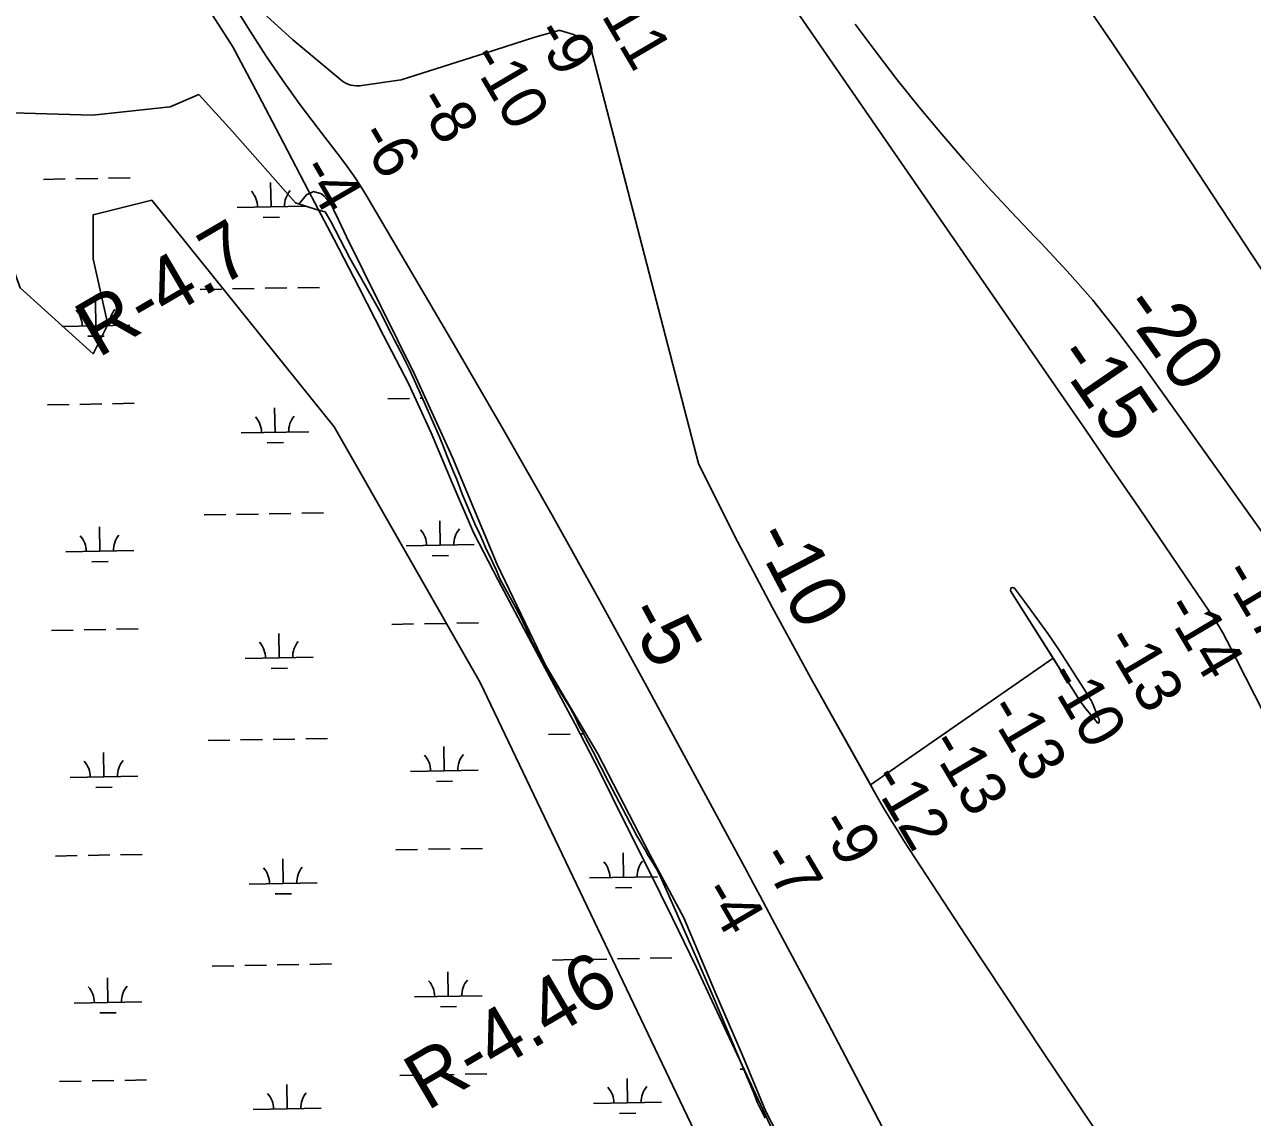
# Model space of a CAD drawing. Extents: x 3914892 to 3953151, y 242587 to 268572.
# Drawn here: x 3932283 to 3934093, y 262785 to 264396 of the extents above; entities that cross this region are included whole.
import ezdxf

# ---------------------------------------------------------------- set-up
doc = ezdxf.new("R2010")
doc.units = 0
for name, color, linetype in [('V-RIVR-EDGE', 7, 'Continuous'), ('V-RIVR-RANG', 7, 'Continuous'), ('V-RIVR-RANG-IDEN', 7, 'Continuous'), ('V-RRAP-FSHR', 7, 'Continuous'), ('V-SITE-VEGE', 7, 'Continuous'), ('V-TOPO-DPTH', 7, 'Continuous'), ('V-TOPO-MINR', 7, 'Continuous'), ('V-TOPO-MINR-IDEN', 7, 'Continuous'), ('V-WETL-SWMP', 7, 'Continuous')]:
    doc.layers.add(name, color=color, linetype=linetype)

msp = doc.modelspace()

# ---------------------------------------------------------------- linework, layer by layer
at = {"layer": 'V-RIVR-EDGE'}
for points in [[(3932741.6, 264116.7), (3932738.6, 264122.1), (3932736.6, 264127.8), (3932731.1, 264135.2), (3932728.1, 264139.1), (3932724.4, 264143.6), (3932720.6, 264146.6), (3932708.8, 264150.3), (3932698.2, 264145.2), (3932693.8, 264139.8), (3932689.3, 264134.6), (3932687.2, 264131.7)], [(3932741.7, 264116.7), (3932757, 264083.5), (3932857.4, 263880.8), (3932913.7, 263757.9), (3932979.2, 263600.3), (3933050.8, 263451.9), (3933127.6, 263320.8), (3933204.4, 263172.4), (3933254.6, 263079.2), (3933300.6, 262969.7), (3933340.6, 262877.6), (3933375.4, 262793.6), (3933432.7, 262683)]]:
    msp.add_lwpolyline(points, dxfattribs=at)
at = {"layer": 'V-RRAP-FSHR'}
msp.add_lwpolyline([(3932546.2, 264430.8), (3932589.8, 264363.8), (3932627.1, 264293.4), (3932664.2, 264222.2), (3932701.3, 264151.3), (3932738.4, 264080.4), (3932775.4, 264009.3), (3932811.6, 263938.1), (3932848.9, 263866.9), (3932882.1, 263794.5), (3932913.1, 263720.8), (3932944.3, 263647.2), (3932980.9, 263576.9), (3933018.8, 263505.6), (3933056.7, 263435.2), (3933094.6, 263364.7), (3933131.2, 263293.6), (3933166.7, 263221.9), (3933202.3, 263150.3), (3933237.9, 263078.6), (3933272.9, 263006.7), (3933306.8, 262934.3), (3933340.8, 262861.8), (3933374.7, 262789.3), (3933408.6, 262716.9)], dxfattribs=at)
at = {"layer": 'V-SITE-VEGE'}
msp.add_lwpolyline([(3934289.5, 260701.2), (3933891.1, 261325.9), (3933417.4, 262456.9), (3932954.5, 263426.4), (3932739.2, 263803.4), (3932470, 264137.3), (3932383.9, 264115.7), (3932383.9, 264051.1), (3932405.4, 263954.2), (3932383.9, 263911.1), (3932276.2, 264008), (3932190.1, 264245), (3932141.4, 264285.3)], dxfattribs=at)
at = {"layer": 'V-TOPO-DPTH'}
for points in [[(3933842.2, 264433.8), (3933887, 264368), (3933931.2, 264301.7), (3934301, 263739.5)], [(3933842.2, 264433.8), (3933887, 264368), (3933931.2, 264301.7), (3934301, 263739.5)], [(3933527.9, 263279.1), (3933442, 263432.6), (3933384.9, 263537.1), (3933329.4, 263642.5), (3933276.3, 263749), (3933117.1, 264363.8), (3933110.2, 264371.5), (3933101.6, 264377.2), (3933091.8, 264381.6), (3933072.3, 264387.5), (3933071.3, 264387.7), (3933070.3, 264387.8), (3933035.1, 264377.8), (3932961.5, 264354.3), (3932838, 264315.2), (3932776.6, 264306.2), (3932772.1, 264306.3), (3932767.7, 264306.5), (3932763.4, 264307.2), (3932759.3, 264308.4), (3932755.5, 264310.3), (3932751.9, 264312.7), (3932678.2, 264373.8), (3932639.8, 264408.9)], [(3933507.4, 264397.1), (3933538.1, 264355.8), (3933569.3, 264315), (3933601.5, 264274.9), (3933634.3, 264235.3), (3933668, 264196.4), (3933702.1, 264157.9), (3933737.1, 264120.3), (3933772.7, 264083.1), (3933780.8, 264074.7), (3933819.8, 264032.8), (3933857.5, 263989.8), (3933893.2, 263945.2), (3933927.5, 263899.4), (3934124, 263624.5)], [(3934124, 263624.5), (3933927.5, 263899.4), (3933893.2, 263945.2), (3933857.5, 263989.8), (3933819.8, 264032.8), (3933780.8, 264074.7), (3933772.7, 264083.1), (3933737.1, 264120.3), (3933702.1, 264157.9), (3933668, 264196.4), (3933634.3, 264235.3), (3933601.5, 264274.9), (3933569.3, 264315), (3933538.1, 264355.8), (3933507.4, 264397.1)], [(3933855.1, 263399.6), (3933853.4, 263402.5), (3933851.7, 263405.5), (3933823.8, 263449.3), (3933807.8, 263473.9), (3933791.3, 263498.2), (3933774.3, 263522.1), (3933756.9, 263545.8), (3933742.2, 263565.2), (3933739.4, 263566.1), (3933737.4, 263565.9), (3933736.5, 263564.1), (3933736.4, 263561.2), (3933795, 263468.3), (3933799, 263462.1), (3933529.9, 263275.5), (3933527.9, 263279.1)], [(3933529.9, 263275.5), (3933799, 263462.1), (3933839, 263398.8), (3933841.1, 263395.6), (3933843.2, 263392.6), (3933845.5, 263389.6), (3933847.8, 263386.7), (3933864.5, 263366.8), (3933865.2, 263366.4), (3933865.7, 263366.3), (3933866.3, 263366.6), (3933866.8, 263367.1), (3933867.2, 263369.1), (3933866.8, 263371), (3933857.9, 263393.4), (3933856.5, 263396.5), (3933855.1, 263399.6)], [(3934096.4, 262422), (3934086.3, 262436.7), (3933900.3, 262709.1), (3933842.4, 262794.4), (3933784.8, 262880), (3933727.8, 262965.9), (3933671.1, 263052), (3933579.1, 263192.9), (3933568.9, 263208.9), (3933558.9, 263225), (3933549.2, 263241.3), (3933539.8, 263257.8), (3933529.9, 263275.5)]]:
    msp.add_lwpolyline(points, dxfattribs=at)
at = {"layer": 'V-TOPO-MINR'}
for points in [[(3932375.9, 264768.2), (3932615.1, 264386.9), (3932638.9, 264350.1), (3932663.5, 264313.8), (3932689, 264278.3), (3932715.3, 264243.2), (3932748.3, 264200.5), (3932758.4, 264187), (3932768.1, 264173.3), (3932777.2, 264159.1), (3932786, 264144.8), (3932915.9, 263924.1), (3932988.6, 263798.8), (3933060.5, 263673), (3933131, 263546.4), (3933200.5, 263419.4), (3933347.8, 263146.8), (3933357.2, 263129.3), (3933366.6, 263111.9), (3933376, 263094.4), (3933385.4, 263076.9), (3933461.8, 262933.8), (3933508.8, 262844.5), (3933555.2, 262754.8)], [(3933359, 264506.7), (3933806.5, 263857.3), (3933846.1, 263799.6), (3933885.7, 263741.9), (3933925.3, 263684.1), (3933964.7, 263626.3), (3934029.3, 263531.5), (3934036.2, 263521), (3934042.8, 263510.2), (3934049.1, 263499.3), (3934055, 263488.2), (3934123.6, 263354)], [(3933842.2, 264433.8), (3933887, 264368), (3933931.2, 264301.7), (3934301, 263739.5)], [(3932639.8, 264408.9), (3932678.2, 264373.8), (3932751.9, 264312.7), (3932755.5, 264310.3), (3932759.3, 264308.4), (3932763.4, 264307.2), (3932767.7, 264306.5), (3932772.1, 264306.3), (3932776.6, 264306.2), (3932838, 264315.2), (3932961.5, 264354.3), (3933035.1, 264377.8), (3933070.3, 264387.8), (3933071.3, 264387.7), (3933072.3, 264387.5), (3933091.8, 264381.6), (3933101.6, 264377.2), (3933110.2, 264371.5), (3933117.1, 264363.8), (3933276.3, 263749), (3933329.4, 263642.5), (3933384.9, 263537.1), (3933442, 263432.6), (3933539.8, 263257.8), (3933549.2, 263241.3), (3933558.9, 263225), (3933568.9, 263208.9), (3933579.1, 263192.9), (3933671.1, 263052), (3933727.8, 262965.9), (3933784.8, 262880), (3933842.4, 262794.4), (3933900.3, 262709.1)], [(3933507.4, 264397.1), (3933538.1, 264355.8), (3933569.3, 264315), (3933601.5, 264274.9), (3933634.3, 264235.3), (3933668, 264196.4), (3933702.1, 264157.9), (3933737.1, 264120.3), (3933772.7, 264083.1), (3933780.8, 264074.7), (3933819.8, 264032.8), (3933857.5, 263989.8), (3933893.2, 263945.2), (3933927.5, 263899.4), (3934124, 263624.5)], [(3933855.1, 263399.6), (3933856.5, 263396.5), (3933857.9, 263393.4), (3933866.8, 263371), (3933867.2, 263369.1), (3933866.8, 263367.1), (3933866.3, 263366.6), (3933865.7, 263366.3), (3933865.2, 263366.4), (3933864.5, 263366.8), (3933847.8, 263386.7), (3933845.5, 263389.6), (3933843.2, 263392.6), (3933841.1, 263395.6), (3933839, 263398.8), (3933736.4, 263561.2), (3933736.5, 263564.1), (3933737.4, 263565.9), (3933739.4, 263566.1), (3933742.2, 263565.2), (3933756.9, 263545.8), (3933774.3, 263522.1), (3933791.3, 263498.2), (3933807.8, 263473.9), (3933823.8, 263449.3), (3933851.7, 263405.5), (3933853.4, 263402.5), (3933855.1, 263399.6)]]:
    msp.add_lwpolyline(points, dxfattribs=at)
at = {"layer": 'V-WETL-SWMP'}
for p, q in [((3932310.4, 264168.2), (3932342.4, 264168.8)), ((3932358.4, 264169.1), (3932390.4, 264169.6)), ((3932406.4, 264169.9), (3932438.4, 264170.5)), ((3932646, 264127.8), (3932645.4, 264163.8)), ((3932596, 264126.9), (3932696, 264128.7)), ((3932634.3, 264112.1), (3932658.3, 264112.5)), ((3932541.3, 264005.8), (3932573.3, 264006.4)), ((3932589.3, 264006.7), (3932621.3, 264007.2)), ((3932637.3, 264007.5), (3932669.3, 264008.1)), ((3932685.3, 264008.4), (3932717.3, 264008.9)), ((3932387.7, 263952.3), (3932387, 263988.3)), ((3932337.7, 263951.4), (3932437.6, 263953.2)), ((3932375.9, 263936.7), (3932399.9, 263937.1)), ((3932316.3, 263835.6), (3932348.3, 263836.1)), ((3932364.3, 263836.4), (3932396.3, 263837)), ((3932412.3, 263837.3), (3932444.3, 263837.9)), ((3932651.9, 263795.1), (3932651.3, 263831.1)), ((3932818.2, 263844.5), (3932850.1, 263845.1)), ((3932866.1, 263845.4), (3932869.3, 263845.5)), ((3932602, 263794.2), (3932701.9, 263796)), ((3932640.2, 263779.5), (3932664.2, 263779.9)), ((3932547.3, 263673.2), (3932579.3, 263673.7)), ((3932595.3, 263674), (3932627.3, 263674.6)), ((3932643.3, 263674.9), (3932675.2, 263675.5)), ((3932691.2, 263675.8), (3932723.2, 263676.3)), ((3932393.6, 263619.7), (3932393, 263655.7)), ((3932895.4, 263628.7), (3932894.8, 263664.6)), ((3932343.6, 263618.8), (3932443.6, 263620.6)), ((3932845.4, 263627.8), (3932945.4, 263629.5)), ((3932883.7, 263613), (3932907.7, 263613.4)), ((3932381.9, 263604), (3932405.9, 263604.5)), ((3932322.3, 263502.9), (3932354.3, 263503.5)), ((3932370.3, 263503.8), (3932402.3, 263504.4)), ((3932418.3, 263504.7), (3932450.3, 263505.2)), ((3932824.1, 263511.9), (3932856.1, 263512.5)), ((3932872.1, 263512.8), (3932904.1, 263513.4)), ((3932920.1, 263513.6), (3932952.1, 263514.2)), ((3932657.9, 263462.5), (3932657.3, 263498.5)), ((3932607.9, 263461.6), (3932707.9, 263463.4)), ((3932646.2, 263446.9), (3932670.2, 263447.3)), ((3932553.2, 263340.6), (3932585.2, 263341.1)), ((3932601.2, 263341.4), (3932633.2, 263342)), ((3932649.2, 263342.3), (3932681.2, 263342.8)), ((3932697.2, 263343.1), (3932729.2, 263343.7)), ((3933055, 263349.5), (3933087, 263350.1)), ((3933103, 263350.4), (3933106.7, 263350.5)), ((3932399.6, 263287.1), (3932398.9, 263323)), ((3932901.4, 263296), (3932900.7, 263332)), ((3932349.6, 263286.2), (3932449.5, 263287.9)), ((3932851.4, 263295.1), (3932951.4, 263296.9)), ((3932387.8, 263271.4), (3932411.8, 263271.8)), ((3932889.7, 263280.4), (3932913.7, 263280.8)), ((3932830.1, 263179.3), (3932862, 263179.9)), ((3932878, 263180.2), (3932910, 263180.7)), ((3932926, 263181), (3932958, 263181.6)), ((3932328.2, 263170.3), (3932360.2, 263170.9)), ((3932376.2, 263171.2), (3932408.2, 263171.8)), ((3932424.2, 263172), (3932456.2, 263172.6)), ((3932663.8, 263129.9), (3932663.2, 263165.9)), ((3933165.7, 263138.9), (3933165, 263174.9)), ((3932613.9, 263129), (3932713.8, 263130.8)), ((3933115.7, 263138), (3933215.7, 263139.8)), ((3933154, 263123.2), (3933177.9, 263123.7)), ((3932652.1, 263114.3), (3932676.1, 263114.7)), ((3933061, 263016.9), (3933093, 263017.5)), ((3933109, 263017.8), (3933141, 263018.3)), ((3933157, 263018.6), (3933189, 263019.2)), ((3933205, 263019.5), (3933237, 263020.1)), ((3932559.2, 263007.9), (3932591.2, 263008.5)), ((3932607.2, 263008.8), (3932639.2, 263009.4)), ((3932655.2, 263009.6), (3932687.1, 263010.2)), ((3932703.1, 263010.5), (3932735.1, 263011.1)), ((3932907.3, 262963.4), (3932906.7, 262999.4)), ((3932405.5, 262954.4), (3932404.9, 262990.4)), ((3932857.3, 262962.5), (3932957.3, 262964.3)), ((3932355.5, 262953.5), (3932455.5, 262955.3)), ((3932895.6, 262947.8), (3932919.6, 262948.2)), ((3932393.8, 262938.8), (3932417.8, 262939.2)), ((3933337.8, 262855.7), (3933343.1, 262855.8)), ((3932334.2, 262837.7), (3932366.2, 262838.3)), ((3932382.2, 262838.6), (3932414.2, 262839.1)), ((3932430.2, 262839.4), (3932462.2, 262840)), ((3932669.8, 262797.3), (3932669.2, 262833.3)), ((3932836, 262846.7), (3932868, 262847.3)), ((3932884, 262847.5), (3932916, 262848.1)), ((3932932, 262848.4), (3932964, 262849)), ((3933171.6, 262806.3), (3933171, 262842.2)), ((3932619.8, 262796.4), (3932719.8, 262798.2)), ((3933121.6, 262805.4), (3933221.6, 262807.1)), ((3933159.9, 262790.6), (3933183.9, 262791))]:
    msp.add_line(p, q, dxfattribs=at)
for points in [[(3932725.9, 264120.3), (3932712.5, 264123.5), (3932682, 264133.4), (3932589.1, 264238.9), (3932539.6, 264293.3), (3932497.5, 264275.3), (3932382.5, 264262.8), (3932230.7, 264267.1)], [(3933374.7, 262783.5), (3933363.2, 262806.4), (3933356.7, 262822.8), (3933343.3, 262855.2), (3933299.4, 262959.7), (3933273.8, 263018.8), (3933240.3, 263094.5), (3933222.7, 263134), (3933218.3, 263144), (3933214.4, 263151.4), (3933210.6, 263157.6), (3933205.5, 263165.6), (3933202.2, 263171.2), (3933197.5, 263179.3), (3933193.1, 263186.6), (3933188.1, 263194.9), (3933185.3, 263199.8), (3933143.5, 263279.6), (3933120.3, 263325), (3933110, 263344.2), (3933105, 263353.7), (3933101.5, 263359.8), (3933097.8, 263367.2), (3933094.8, 263374.1), (3933090.9, 263381.6), (3933087, 263388.8), (3933082.8, 263395.5), (3933078.6, 263402), (3933074.6, 263408.4), (3933066.2, 263422.2), (3933056.7, 263440.2), (3933050.5, 263450.9), (3933043.4, 263463.1), (3933038.6, 263471.7), (3933032, 263483.8), (3933029.4, 263488.8), (3933026, 263496.4), (3933022, 263505.9), (3933017.8, 263515), (3933012.3, 263525.9), (3933006.3, 263537.1), (3932983.5, 263579), (3932978.5, 263591.2), (3932974.1, 263600.9), (3932968.9, 263611.3), (3932963.7, 263622), (3932958.6, 263633.6), (3932953.2, 263645.7), (3932946.7, 263660), (3932928.5, 263702.7), (3932920.1, 263725.6), (3932915.1, 263736.7), (3932910.1, 263748.5), (3932905.4, 263760.9), (3932900.5, 263773.5), (3932894.6, 263788.4), (3932868.5, 263847.3), (3932849.9, 263887.7), (3932845.4, 263897.5), (3932840.6, 263907.1), (3932836.3, 263915.3), (3932831.9, 263923.7), (3932828.1, 263931.2), (3932823.1, 263940.7), (3932806.2, 263973.6), (3932762.2, 264051.9), (3932733.9, 264105.8), (3932725.9, 264120.3)]]:
    msp.add_lwpolyline(points, dxfattribs=at)
for centre, start, end in [((3932590.8, 264127.2), 0.2532, 41.7968), ((3932701.2, 264129.2), 140.2532, 181.7968), ((3932332.4, 263951.8), 0.2532, 41.7968), ((3932442.9, 263953.8), 140.2532, 181.7968), ((3932596.7, 263794.6), 0.2532, 41.7968), ((3932707.2, 263796.6), 140.2532, 181.7968), ((3932840.2, 263628.1), 0.2532, 41.7968), ((3932950.7, 263630.1), 140.2532, 181.7968), ((3932338.4, 263619.2), 0.2532, 41.7968), ((3932448.8, 263621.1), 140.2532, 181.7968), ((3932602.7, 263462), 0.2532, 41.7968), ((3932713.1, 263464), 140.2532, 181.7968), ((3932344.3, 263286.5), 0.2532, 41.7968), ((3932454.8, 263288.5), 140.2532, 181.7968), ((3932846.1, 263295.5), 0.2532, 41.7968), ((3932956.6, 263297.5), 140.2532, 181.7968), ((3933110.4, 263138.4), 0.2532, 41.7968), ((3933220.9, 263140.3), 140.2532, 181.7968), ((3932608.6, 263129.4), 0.2532, 41.7968), ((3932719.1, 263131.4), 140.2532, 181.7968), ((3932460.7, 262955.9), 140.2532, 181.7968), ((3932852.1, 262962.9), 0.2532, 41.7968), ((3932962.6, 262964.9), 140.2532, 181.7968), ((3932350.3, 262953.9), 0.2532, 41.7968), ((3932614.6, 262796.8), 0.2532, 41.7968), ((3932725, 262798.7), 140.2532, 181.7968), ((3933116.4, 262805.7), 0.2532, 41.7968), ((3933226.9, 262807.7), 140.2532, 181.7968)]:
    msp.add_arc(centre, 35.2, start, end, dxfattribs=at)

# ---------------------------------------------------------------- texts
at = {"layer": 'V-RIVR-RANG'}
for s, rotation, p in [('-11', 300.439, (3933117, 264435.8)), ('-9', 300.439, (3933031.5, 264384)), ('-10', 300.439, (3932936.8, 264347.6)), ('-8', 300.439, (3932858.4, 264283.7)), ('-6', 300.439, (3932772.3, 264232.8)), ('-4', 300.1583, (3932686.2, 264182.4)), ('-17', 300.6478, (3934046, 263587.3)), ('-14', 300.6478, (3933960.2, 263536.1)), ('-13', 300.6478, (3933872.3, 263488.2)), ('-10', 300.6478, (3933787.3, 263435.4)), ('-13', 300.6478, (3933699.9, 263386.7)), ('-13', 300.6478, (3933613.8, 263335.9)), ('-12', 300.6478, (3933527.9, 263284.7)), ('-9', 300.6478, (3933451, 263218.3)), ('-7', 300.6478, (3933364.6, 263168)), ('-4', 300.3683, (3933278.8, 263117))]:
    msp.add_text(s, height=67, rotation=rotation, dxfattribs=at).set_placement(p)
at = {"layer": 'V-RIVR-RANG-IDEN'}
for s, rotation, p in [('R-4.7', 30.3053, (3932391, 263904.1)), ('R-4.46', 30.5022, (3932875.9, 262793.6))]:
    msp.add_text(s, height=83, rotation=rotation, dxfattribs=at).set_placement(p)
at = {"layer": 'V-TOPO-MINR-IDEN'}
for s, rotation, p in [('-20', 305.5562, (3933896.9, 263979.5)), ('-15', 304.5239, (3933799.3, 263906.1)), ('-10', 297.781, (3933354.9, 263640.9)), ('-5', 298.6979, (3933165.9, 263527.9))]:
    msp.add_text(s, height=83, rotation=rotation, dxfattribs=at).set_placement(p)

doc.saveas('drawing.dxf')
